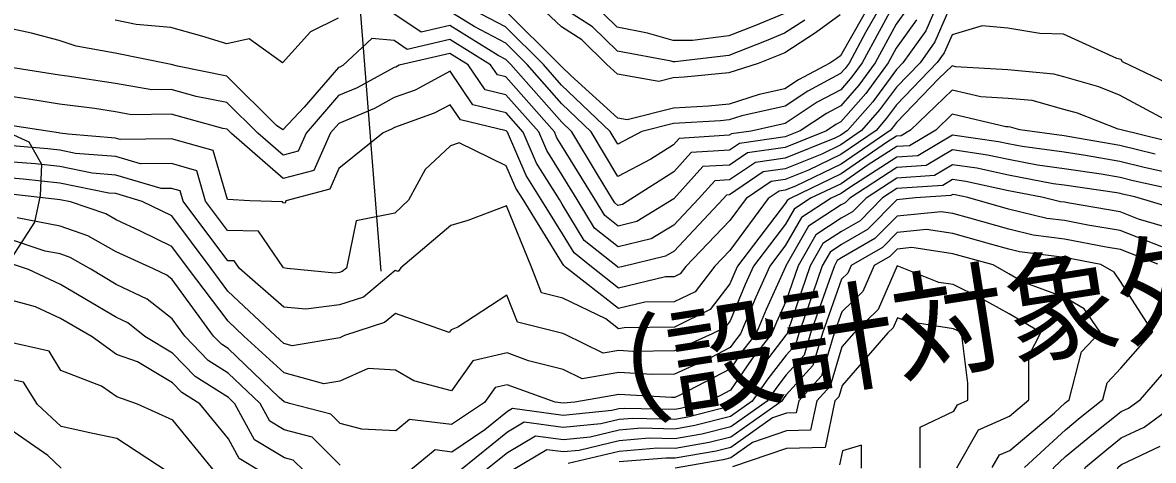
# Model space of a CAD drawing. Extents: x 42655 to 43811, y -141820 to -141156.
# Drawn here: x 43313.5 to 43416.6, y -141436.2 to -141396.2 of the extents above; entities that cross this region are included whole.
import ezdxf

# ---------------------------------------------------------------- set-up
doc = ezdxf.new("R2010")
doc.units = 0
for name, color, linetype in [('D-BMK-HTXT_1', 7, 'Continuous'), ('D-STR-HTXT', 7, 'Continuous'), ('ZE_HICN', 7, 'Continuous'), ('ZE_LWCN', 7, 'Continuous'), ('地形', 7, 'Continuous'), ('現況道路ﾊｯﾁ', 7, 'Continuous')]:
    doc.layers.add(name, color=color, linetype=linetype)

msp = doc.modelspace()

# ---------------------------------------------------------------- linework, layer by layer
at = {"layer": 'D-BMK-HTXT_1'}
msp.add_line((43339.88, -141340.17), (43346.16, -141418.91), dxfattribs=at)
at = {"layer": 'ZE_HICN'}
for points in [[(43388.05, -141395.54), (43385.78, -141397.18), (43382.98, -141399), (43382.4, -141399.25), (43380.56, -141399.97), (43377.9, -141400.81), (43373.82, -141401.21), (43372.82, -141401.27), (43371.5, -141401.6), (43367.73, -141400.93), (43366.74, -141400.03), (43364.47, -141397.8), (43362.62, -141396.62), (43359.75, -141393.9)], [(43394.15, -141394.97), (43393.15, -141396.39), (43391.24, -141399.92), (43389.75, -141401.94), (43388.09, -141403.83), (43386.79, -141404.52), (43384.39, -141406.11), (43383.02, -141406.67), (43378.86, -141407.26), (43377.94, -141407.88), (43374.45, -141408.09), (43372.86, -141409.85), (43368.96, -141412.35), (43368.18, -141412.83), (43367.78, -141412.92), (43367.5, -141412.69), (43367.29, -141412.35), (43365.91, -141410.11), (43363.57, -141406.21), (43362.66, -141405.33), (43358.02, -141400.07), (43357.54, -141399.6), (43356.84, -141399.23), (43352.44, -141396.51), (43349.84, -141397.1), (43347.35, -141395.43)], [(43342.26, -141395.82), (43339.74, -141397.09), (43337.19, -141399.92), (43334.13, -141397.72), (43332.1, -141398.18), (43329.84, -141397.48), (43327, -141396.68), (43323.84, -141396.41), (43321.91, -141396.01)], [(43418.11, -141405.32), (43413.53, -141402.86), (43411.63, -141402.11), (43408.43, -141401.2), (43407.52, -141400.95), (43403.34, -141400.54), (43398.57, -141400.27), (43398.25, -141400.19), (43397.05, -141401.35), (43393.19, -141405.35), (43392.91, -141405.73), (43392.61, -141406.07), (43388.12, -141409.17), (43383.97, -141411.15), (43383.04, -141411.53), (43382.49, -141411.61), (43381.48, -141412.29), (43377.98, -141417.03), (43376.6, -141418.47), (43374.82, -141420.79), (43372.91, -141421.73), (43370.23, -141421.76), (43367.83, -141422.32), (43363, -141418.54), (43362.83, -141418.4), (43362.72, -141418.21), (43359.14, -141412.39), (43358.47, -141411.34), (43357.59, -141409.3), (43353.28, -141407.21), (43352.49, -141407.48), (43350.19, -141409.64), (43348.66, -141412.44), (43347.43, -141413.62), (43343.89, -141414.34), (43343.03, -141418.63), (43342.64, -141418.96), (43342.37, -141419.05), (43341.99, -141419.1), (43337.62, -141418.66), (43337.28, -141418.6), (43334.98, -141415.28), (43332.18, -141415.22), (43330.17, -141412.53), (43329.36, -141409.75), (43327.06, -141409.1), (43324.24, -141409.14), (43321.97, -141408.47), (43318.32, -141408.17), (43316.88, -141407.88), (43315.79, -141407.75), (43311.79, -141407.42)], [(43418.67, -141413.25), (43414.91, -141412.13), (43413.78, -141411.88), (43413.57, -141411.83), (43413.27, -141411.78), (43408.48, -141411.08), (43407.47, -141410.94), (43403.39, -141410.17), (43400.5, -141409.53), (43398.3, -141409.21), (43396.63, -141410.2), (43393.21, -141410.42), (43390.4, -141412.25), (43389.17, -141413.5), (43388.14, -141414.09), (43385.81, -141415.6), (43384.2, -141418.44), (43383.09, -141421.7), (43382.24, -141423.57), (43381.8, -141424.61), (43379.96, -141426.97), (43378.04, -141429.78), (43376.08, -141430.8), (43373.49, -141431.46), (43372.96, -141431.55), (43368.37, -141431.44), (43367.87, -141431.48), (43367.21, -141431.64), (43362.79, -141432.08), (43358.16, -141431.45), (43357.7, -141431.73), (43355.64, -141433.4), (43352.63, -141435.42), (43351.1, -141435.23), (43348.86, -141437.09)], [(43342.45, -141436.63), (43339.88, -141434.07), (43337.35, -141433.4), (43336.02, -141432.6), (43335.14, -141430.99), (43332.24, -141428.22), (43330.41, -141427.06), (43328.28, -141424.86), (43327.13, -141423.28), (43324.85, -141421.46), (43322.02, -141420.12), (43319.7, -141418.74), (43317.82, -141417.66), (43316.92, -141417.35), (43315.54, -141417.08), (43311.83, -141415.84)], [(43401.9, -141436.84), (43402.56, -141435.69), (43403.51, -141435.27), (43407.59, -141431.85), (43408.57, -141430.94), (43408.72, -141430.82), (43408.94, -141430.65), (43410.05, -141426.29), (43411.74, -141424.47), (43410.29, -141422.35), (43408.53, -141421.33), (43404.74, -141419.92), (43403.43, -141419.15), (43401.99, -141418.35), (43398.33, -141417.34), (43394.58, -141416.77), (43393.24, -141416.91), (43392.58, -141417.59), (43391.15, -141418.4), (43390.11, -141420.76), (43388.18, -141422.64), (43387.49, -141424.58), (43386.33, -141428.47), (43384.27, -141430.76), (43384.04, -141431.85), (43383.14, -141431.88), (43381.87, -141432.31), (43378.06, -141435), (43376.73, -141435.34), (43372.98, -141435.99), (43372.15, -141435.97), (43367.89, -141436.33)], [(43317.01, -141436.9), (43315.77, -141435.75), (43311.91, -141433.07), (43310.09, -141435.06), (43306.82, -141433.34), (43305.41, -141432.85), (43301.72, -141431.35), (43298.49, -141433.4), (43296.65, -141434.8), (43293.26, -141437.35)]]:
    msp.add_lwpolyline(points, dxfattribs=at)
at = {"layer": 'ZE_LWCN'}
for points in [[(43398.23, -141394.42), (43396.68, -141398), (43395.34, -141399.9), (43393.17, -141402.14), (43391.64, -141404.21), (43390, -141406.08), (43388.11, -141407.39), (43386.36, -141408.23), (43383.03, -141409.59), (43381.03, -141409.87), (43377.96, -141411.95), (43377.68, -141411.97), (43377.37, -141412.31), (43372.89, -141417.09), (43372.12, -141417.56), (43368.13, -141418.51), (43367.81, -141418.59), (43367.72, -141418.52), (43364.7, -141416.12), (43362.69, -141412.81), (43362.43, -141412.38), (43360.34, -141409.05), (43359.12, -141406.23), (43357.57, -141404.47), (43354.54, -141403.75), (43352.46, -141400.68), (43349.27, -141402.4), (43347.38, -141403.08), (43345.56, -141404.08), (43342.31, -141405.44), (43341.56, -141406.31), (43340.04, -141409.72), (43337.24, -141410.45), (43332.52, -141406.36), (43332.13, -141405.97), (43331.75, -141405.89), (43327.04, -141404.59), (43323.4, -141404.64), (43321.95, -141404.39), (43320.03, -141404.09), (43316.86, -141403.68), (43314.22, -141403.25), (43311.77, -141402.88)], [(43397.25, -141393.73), (43395.84, -141396.99), (43393.77, -141399.9), (43393.17, -141400.53), (43391.01, -141403.46), (43388.7, -141406.09), (43388.11, -141406.5), (43387.55, -141406.77), (43383.03, -141408.62), (43380.31, -141409), (43377.95, -141410.59), (43376.6, -141410.68), (43375.12, -141412.32), (43372.88, -141414.71), (43370.81, -141415.98), (43367.8, -141416.7), (43365.63, -141414.98), (43364.05, -141412.37), (43362.68, -141410.15), (43361.28, -141407.91), (43360.55, -141406.22), (43357.56, -141402.83), (43355.66, -141402.38), (43354.11, -141400.09), (43352.45, -141399.06), (43347.83, -141400.12), (43347.51, -141400.29), (43347.37, -141400.34), (43343.98, -141402.19), (43342.3, -141402.9), (43339.33, -141406.32), (43338.6, -141407.98), (43337.23, -141408.34), (43334.93, -141406.34), (43332.12, -141403.54), (43329.32, -141402.98), (43327.03, -141402.35), (43325.26, -141402.37), (43321.94, -141401.8), (43317.56, -141401.13), (43316.85, -141401.03), (43312.23, -141400.29)], [(43393.14, -141394.2), (43390.05, -141399.92), (43389.12, -141401.18), (43388.09, -141402.36), (43385.94, -141403.5), (43383.01, -141405.44), (43379.93, -141406.13), (43378.13, -141406.39), (43377.93, -141406.52), (43373.37, -141406.8), (43372.85, -141407.38), (43370.76, -141408.71), (43367.77, -141410.29), (43365.32, -141406.2), (43362.65, -141403.64), (43359.5, -141400.07), (43357.54, -141398.12), (43354.65, -141396.6), (43352.44, -141395.23)], [(43392.29, -141393.75), (43390.36, -141397.14), (43388.85, -141399.93), (43388.49, -141400.42), (43388.08, -141400.89), (43385.09, -141402.48), (43383.01, -141403.86), (43379.07, -141404.75), (43377.92, -141405.11), (43377.13, -141405.19), (43372.84, -141405.45), (43369.96, -141406.18), (43367.76, -141407.34), (43367.07, -141406.19), (43362.64, -141401.95), (43360.98, -141400.06), (43357.53, -141396.63), (43352.45, -141393.96)], [(43391.21, -141393.75), (43388.07, -141399.28), (43387.73, -141399.52), (43387.1, -141399.94), (43384.24, -141401.46), (43383, -141402.28), (43380.66, -141402.81), (43377.92, -141403.68), (43376.03, -141403.86), (43372.83, -141404.06), (43368.63, -141405.12), (43367.75, -141404.96), (43363.48, -141401.06), (43362.64, -141400.25), (43362.46, -141400.05), (43357.52, -141395.15)], [(43384.81, -141396.01), (43382.97, -141397.21), (43381.28, -141397.91), (43377.9, -141399.24), (43372.96, -141399.83), (43372.81, -141399.83), (43372.62, -141399.77), (43367.72, -141398.83), (43365.45, -141396.61), (43362.61, -141394.8)], [(43382.97, -141395.41), (43380.17, -141396.57), (43377.89, -141397.46), (43374.56, -141397.86), (43372.8, -141397.88), (43370.47, -141397.19), (43367.71, -141396.66), (43366.43, -141395.41)], [(43395, -141395.98), (43393.16, -141398.57), (43392.43, -141399.91), (43390.38, -141402.7), (43388.1, -141405.3), (43387.64, -141405.54), (43386.8, -141406.1), (43383.02, -141407.64), (43379.58, -141408.13), (43377.94, -141409.24), (43375.52, -141409.38), (43372.87, -141412.33), (43369.49, -141414.4), (43367.79, -141414.81), (43366.57, -141413.84), (43365.67, -141412.36), (43362.67, -141407.49), (43362.21, -141406.76), (43361.98, -141406.22), (43357.55, -141401.19), (43356.78, -141401.01), (43356.16, -141400.08), (43352.45, -141397.79), (43348.55, -141398.68), (43347.36, -141397.87), (43345.33, -141397.68), (43342.69, -141400.15), (43342.41, -141400.3), (43342.28, -141400.35), (43339.17, -141403.95), (43337.22, -141406.03), (43336.63, -141405.62), (43332.11, -141401.12), (43327.61, -141400.22), (43327.02, -141400.05), (43326.87, -141400.04), (43321.92, -141399.04), (43318.37, -141398.4), (43316.83, -141397.86), (43314.28, -141397.2), (43311.74, -141396.64)], [(43418.61, -141402.13), (43413.8, -141399.81), (43413.67, -141399.62), (43413.51, -141399.57), (43413.26, -141399.51), (43408.42, -141397.29), (43406.25, -141397.23), (43403.32, -141396.76), (43400.99, -141396.54), (43398.24, -141397.36), (43397.53, -141399.01), (43396.9, -141399.89), (43393.18, -141403.74), (43392.28, -141404.97), (43391.31, -141406.08), (43388.11, -141408.28), (43385.16, -141409.69), (43383.04, -141410.56), (43381.76, -141410.74), (43379.46, -141412.3), (43377.97, -141414.31), (43373.97, -141418.49), (43373.46, -141419.16), (43372.9, -141419.43), (43372.12, -141419.44), (43367.82, -141420.46), (43365.36, -141418.53), (43363.77, -141417.26), (43362.71, -141415.51), (43360.78, -141412.39), (43359.41, -141410.19), (43357.69, -141406.24), (43357.58, -141406.11), (43353.42, -141405.12), (43352.48, -141403.73), (43351.03, -141404.51), (43347.4, -141405.82), (43347.13, -141405.96), (43346.36, -141406.29), (43342.33, -141409.56), (43341.49, -141411.45), (43337.5, -141412.5), (43337.42, -141412.7), (43337.25, -141412.67), (43337.19, -141412.58), (43334.2, -141412.51), (43332.16, -141412.38), (43330.87, -141407.9), (43327.05, -141406.84), (43322.37, -141406.9), (43321.96, -141406.78), (43317.65, -141406.43), (43316.87, -141406.32), (43316.77, -141406.31), (43311.78, -141405.55)], [(43417.75, -141407.03), (43413.54, -141406), (43413.39, -141405.97), (43409.67, -141404.51), (43408.45, -141404.16), (43405.54, -141403.36), (43403.35, -141403.15), (43400.86, -141403.01), (43398.26, -141402.39), (43394.46, -141406.06), (43393.61, -141406.57), (43393.19, -141406.6), (43392.27, -141407.19), (43388.12, -141410.05), (43383.48, -141412.28), (43383.2, -141412.46), (43383.05, -141412.72), (43378.68, -141418.46), (43378.43, -141419), (43377.99, -141420.06), (43376.18, -141422.43), (43372.92, -141424.03), (43368.33, -141424.08), (43367.84, -141424.19), (43366.67, -141423.28), (43362.74, -141421.38), (43360.79, -141420.9), (43359.89, -141418.55), (43357.61, -141412.96), (43354.09, -141414.31), (43352.53, -141414.75), (43347.99, -141418.61), (43347.74, -141418.95), (43347.46, -141418.85), (43344.57, -141421.28), (43342.39, -141422), (43339.3, -141422.39), (43337.3, -141422.19), (43333.25, -141418.68), (43332.77, -141417.98), (43332.19, -141417.97), (43328.13, -141412.54), (43327.86, -141411.59), (43327.07, -141411.37), (43326.11, -141411.38), (43321.98, -141410.15), (43319.83, -141409.98), (43316.89, -141409.38), (43314.66, -141409.13), (43311.79, -141408.9)], [(43416.76, -141408.24), (43413.55, -141407.46), (43409, -141406.65), (43408.46, -141406.57), (43404.43, -141406.02), (43403.57, -141405.78), (43403.37, -141405.76), (43403.14, -141405.75), (43398.27, -141404.59), (43396.76, -141406.05), (43394.36, -141407.48), (43393.2, -141407.55), (43390.6, -141409.23), (43388.13, -141410.94), (43385.35, -141412.27), (43383.85, -141413.25), (43383.06, -141414.64), (43380.15, -141418.46), (43379.38, -141420.14), (43378.01, -141423.44), (43377.54, -141424.06), (43376.37, -141424.64), (43372.93, -141426.2), (43369.14, -141426.24), (43367.85, -141426.16), (43366.43, -141426.41), (43362.95, -141424.7), (43362.75, -141424.6), (43358.6, -141423.57), (43357.65, -141421.1), (43353.17, -141424.02), (43352.57, -141424.28), (43352.39, -141424.53), (43347.48, -141422.77), (43346.5, -141423.59), (43342.85, -141424.8), (43342.4, -141425), (43338.06, -141425.72), (43337.31, -141425.52), (43336.55, -141424.83), (43332.2, -141420.73), (43330.67, -141418.69), (43327.08, -141413.88), (43324.39, -141412.56), (43321.98, -141411.84), (43321.34, -141411.79), (43316.89, -141410.89), (43313.54, -141410.51), (43311.8, -141410.37)], [(43418.65, -141410.09), (43415.77, -141409.46), (43413.56, -141408.92), (43410.42, -141408.36), (43408.47, -141408.07), (43404.64, -141407.55), (43403.37, -141407.31), (43402.48, -141407.11), (43398.28, -141406.51), (43395.12, -141408.38), (43393.2, -141408.51), (43388.93, -141411.28), (43388.13, -141411.83), (43387.23, -141412.26), (43384.5, -141414.03), (43383.07, -141416.56), (43381.63, -141418.45), (43380.34, -141421.29), (43378.94, -141424.63), (43378.49, -141425.2), (43378.02, -141425.89), (43376.21, -141426.84), (43372.94, -141428.33), (43370.9, -141428.35), (43367.86, -141428.16), (43364.52, -141428.74), (43362.77, -141427.88), (43359.63, -141427.09), (43357.67, -141426.38), (43354.53, -141427.1), (43352.6, -141429.85), (43349.15, -141428.93), (43347.5, -141427.95), (43345.01, -141427.81), (43342.42, -141428.95), (43340.95, -141429.19), (43337.33, -141428.18), (43333.65, -141424.84), (43332.22, -141423.49), (43328.61, -141418.7), (43327.1, -141416.67), (43324.23, -141415.26), (43322, -141414.23), (43321.06, -141413.7), (43317.85, -141412.59), (43316.9, -141412.4), (43312.41, -141411.89)], [(43418.66, -141411.52), (43414.77, -141410.67), (43413.57, -141410.37), (43411.85, -141410.07), (43408.47, -141409.57), (43406.05, -141409.24), (43403.38, -141408.74), (43401.49, -141408.32), (43398.29, -141407.86), (43395.88, -141409.29), (43393.21, -141409.47), (43388.91, -141412.25), (43388.49, -141412.68), (43388.14, -141412.88), (43385.16, -141414.82), (43383.1, -141418.44), (43383.07, -141418.51), (43381.29, -141422.43), (43380.37, -141424.62), (43379.23, -141426.08), (43378.03, -141427.84), (43373.43, -141430.24), (43372.95, -141430.45), (43372.66, -141430.46), (43367.86, -141430.16), (43363.85, -141430.86), (43362.78, -141430.96), (43362.06, -141430.87), (43357.68, -141429.29), (43356.57, -141429.54), (43355.62, -141430.9), (43352.61, -141432.92), (43348.77, -141432.44), (43347.53, -141433.48), (43344.42, -141433.35), (43342.44, -141432.82), (43341.59, -141431.98), (43337.81, -141430.98), (43337.34, -141430.85), (43336.88, -141430.44), (43332.23, -141425.98), (43331.61, -141425.59), (43330.89, -141424.85), (43327.11, -141419.68), (43326.63, -141419.29), (43325.41, -141418.72), (43322.01, -141417.15), (43319.44, -141415.68), (43316.91, -141414.81), (43313, -141414.04)], [(43418.68, -141415.17), (43415.26, -141414.16), (43413.58, -141413.5), (43408.95, -141412.72), (43408.49, -141412.63), (43408.14, -141412.59), (43406.42, -141412.17), (43403.39, -141411.6), (43399.51, -141410.73), (43398.3, -141410.56), (43397.39, -141411.1), (43393.22, -141411.38), (43391.89, -141412.24), (43389.85, -141414.32), (43388.15, -141415.3), (43386.47, -141416.39), (43385.3, -141418.43), (43383.27, -141424.4), (43383.2, -141424.61), (43383.17, -141424.69), (43383.1, -141424.77), (43380.7, -141427.85), (43378.69, -141430.79), (43378.05, -141431.24), (43374.14, -141432.24), (43372.96, -141432.44), (43369.12, -141432.35), (43367.88, -141432.45), (43366.22, -141432.85), (43362.79, -141433.19), (43359.21, -141432.7), (43357.7, -141433.6), (43353.43, -141437.07)], [(43417.39, -141416.71), (43413.59, -141415.22), (43410.62, -141414.72), (43408.5, -141414.31), (43406.89, -141414.11), (43403.4, -141413.26), (43399.69, -141412.2), (43398.53, -141411.94), (43398.31, -141411.91), (43398.14, -141412.01), (43394.92, -141412.22), (43393.22, -141412.4), (43390.53, -141415.13), (43388.15, -141416.5), (43387.12, -141417.17), (43386.41, -141418.43), (43385.16, -141422.09), (43384.27, -141424.6), (43383.96, -141425.64), (43383.11, -141426.58), (43381.43, -141428.73), (43380.03, -141430.78), (43378.05, -141432.18), (43374.79, -141433.01), (43372.97, -141433.33), (43369.88, -141433.25), (43367.88, -141433.42), (43365.23, -141434.06), (43362.8, -141434.3), (43360.25, -141433.96), (43357.71, -141435.48), (43355.76, -141437.06)], [(43417.01, -141418.28), (43413.6, -141416.94), (43412.29, -141416.72), (43408.5, -141415.99), (43405.64, -141415.63), (43403.41, -141415.09), (43399.87, -141414.08), (43398.32, -141413.65), (43397.26, -141413.49), (43393.23, -141413.9), (43391.21, -141415.95), (43388.16, -141417.71), (43387.78, -141417.96), (43387.51, -141418.42), (43387.05, -141419.78), (43385.35, -141424.59), (43384.75, -141426.58), (43383.12, -141428.39), (43382.17, -141429.61), (43381.37, -141430.78), (43378.06, -141433.12), (43375.43, -141433.79), (43372.97, -141434.22), (43370.63, -141434.16), (43367.88, -141434.39), (43364.24, -141435.27), (43362.8, -141435.41), (43361.29, -141435.21), (43358.23, -141437.05)], [(43404.85, -141436.83), (43408.59, -141433.39), (43409.93, -141432.28), (43412.01, -141430.63), (43412.39, -141429.1), (43413.65, -141427.76), (43416.55, -141424.45), (43413.61, -141419.86), (43413.03, -141419), (43411.82, -141418.31), (43408.51, -141417.67), (43404.4, -141417.16), (43403.42, -141416.92), (43401.87, -141416.48), (43398.32, -141415.49), (43395.92, -141415.13), (43393.24, -141415.4), (43391.89, -141416.77), (43389.03, -141418.41), (43388.73, -141419.1), (43388.17, -141419.65), (43386.42, -141424.59), (43385.54, -141427.53), (43383.13, -141430.21), (43382.9, -141430.49), (43382.72, -141430.77), (43378.06, -141434.06), (43376.08, -141434.56), (43372.98, -141435.11), (43371.39, -141435.07), (43367.89, -141435.36), (43363.25, -141436.48)], [(43339.15, -141437.14), (43338.17, -141436.16), (43337.36, -141435.95), (43334.63, -141434.3), (43332.83, -141431.01), (43332.25, -141430.45), (43329.21, -141428.53), (43327.14, -141426.39), (43324.64, -141424.88), (43323.08, -141423.63), (43322.04, -141423.14), (43319.16, -141421.44), (43316.94, -141420.15), (43314.03, -141418.77), (43311.84, -141418.03)], [(43398.68, -141436.86), (43400.65, -141433.4), (43403.49, -141432.14), (43405.26, -141430.66), (43405.24, -141426.65), (43406.34, -141424.5), (43403.45, -141422.8), (43400.81, -141421.34), (43398.35, -141420.14), (43397.05, -141419.94), (43393.25, -141418.44), (43391.5, -141422.42), (43389.28, -141424.58), (43388.2, -141425.81), (43387.12, -141429.42), (43385.92, -141430.75), (43385.35, -141433.43), (43383.15, -141433.48), (43380.05, -141434.54), (43378.07, -141435.94), (43377.37, -141436.12), (43372.98, -141436.88)], [(43335.16, -141437.16), (43333.24, -141436), (43332.27, -141434.22), (43329.64, -141431.02), (43328.01, -141429.99), (43327.15, -141429.1), (43323.95, -141427.18), (43322.05, -141426.52), (43319.82, -141424.9), (43316.95, -141423.25), (43314.66, -141422.16), (43311.85, -141421.4)], [(43395.35, -141436.87), (43395.33, -141433.14), (43398.4, -141431.7), (43398.74, -141431.11), (43399.69, -141430.69), (43399.68, -141429.13), (43399.11, -141424.53), (43398.37, -141424.17), (43394.13, -141423.52), (43393.27, -141423.18), (43392.88, -141424.08), (43392.38, -141424.56), (43388.21, -141429.34), (43387.91, -141430.37), (43387.56, -141430.75), (43386.66, -141435), (43383.15, -141435.09), (43378.22, -141436.78)], [(43330.99, -141437.18), (43327.17, -141432.52), (43323.96, -141431.05), (43322.07, -141430.4), (43320.69, -141429.4), (43316.97, -141427.97), (43315.89, -141426.22), (43311.87, -141425.31), (43308.12, -141426.57), (43306.79, -141427.41), (43304.48, -141428.33), (43301.7, -141427.25), (43298.02, -141429.48), (43296.63, -141430.27), (43296.2, -141430.66), (43295.56, -141431.18), (43291.56, -141434.4), (43290.39, -141435.94), (43288.99, -141437.37)], [(43418.85, -141452.34), (43415.62, -141451.35), (43413.76, -141450.75), (43410.06, -141449.13), (43408.65, -141447.72), (43405.62, -141442.99), (43406.27, -141440.15), (43407.53, -141436.82), (43408.6, -141435.83), (43411.14, -141433.73), (43413.67, -141431.73), (43414.33, -141431.42), (43415.42, -141430.62), (43418.73, -141426.8)], [(43326.68, -141437.2), (43322.09, -141434.19), (43319.89, -141433.73), (43317, -141433.1), (43314.83, -141431.09), (43313.57, -141429.06), (43311.89, -141428.68), (43310.32, -141429.21), (43307.26, -141431.13), (43307.03, -141431.39), (43306.81, -141431.27), (43306.72, -141431.24), (43306.45, -141431.13), (43301.71, -141429.3), (43298.62, -141431.17), (43297.32, -141431.99), (43296.64, -141432.5), (43293.79, -141434.66), (43291.57, -141436.44)], [(43418.84, -141450.67), (43413.75, -141449.11), (43408.64, -141444.01), (43407.97, -141442.98), (43408.12, -141442.35), (43408.62, -141441.01), (43410.4, -141436.8), (43412.36, -141435.19), (43413.68, -141434.14), (43415.77, -141433.16), (43418.75, -141430.96)], [(43390, -141436.9), (43389.99, -141434.78), (43388.24, -141435.31), (43387.97, -141436.58)], [(43418.84, -141448.92), (43415.59, -141446.86), (43413.74, -141446.41), (43410.46, -141442.96), (43413.07, -141437.54), (43413.39, -141436.79), (43413.57, -141436.64), (43413.69, -141436.55), (43417.22, -141434.89)]]:
    msp.add_lwpolyline(points, dxfattribs=at)
at = {"layer": '地形'}
msp.add_lwpolyline([(43311.55, -141419.15), (43314.59, -141414.46), (43315.12, -141412.01), (43315.24, -141409.2), (43314.07, -141407.15), (43312.02, -141406.21)], dxfattribs=at)
at = {"layer": '現況道路ﾊｯﾁ'}
msp.add_lwpolyline([(43311.55, -141419.15), (43314.59, -141414.46), (43315.12, -141412.01), (43315.24, -141409.2), (43314.07, -141407.15), (43312.02, -141406.21)], dxfattribs=at)

# ---------------------------------------------------------------- texts
at = {"layer": 'D-STR-HTXT'}
msp.add_text('（設計対象外）', height=7.966, rotation=8.8832, dxfattribs=at).set_placement((43362.79, -141433.16))

doc.saveas('drawing.dxf')
